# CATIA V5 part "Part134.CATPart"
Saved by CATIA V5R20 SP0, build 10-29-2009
Part number: FA 084700-3
Revision: ANY
Definition: UNKNOWN
Nomenclature: FA 084700-3
Source: Unknown
Bounding box of the stored display mesh (mm): x -2.687 to 2.687, y -2.475 to 2.475, z -2.5 to 2.5
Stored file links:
  C:\Users\Utente\Desktop\IO LAVORO\3D X SITO CF\CUMSA\3D files FA\FA 084712-20\Part134.CATPart

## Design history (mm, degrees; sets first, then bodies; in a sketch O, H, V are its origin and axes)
Body1 "Chaflán4" (main body)
  Solid1: solid without history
